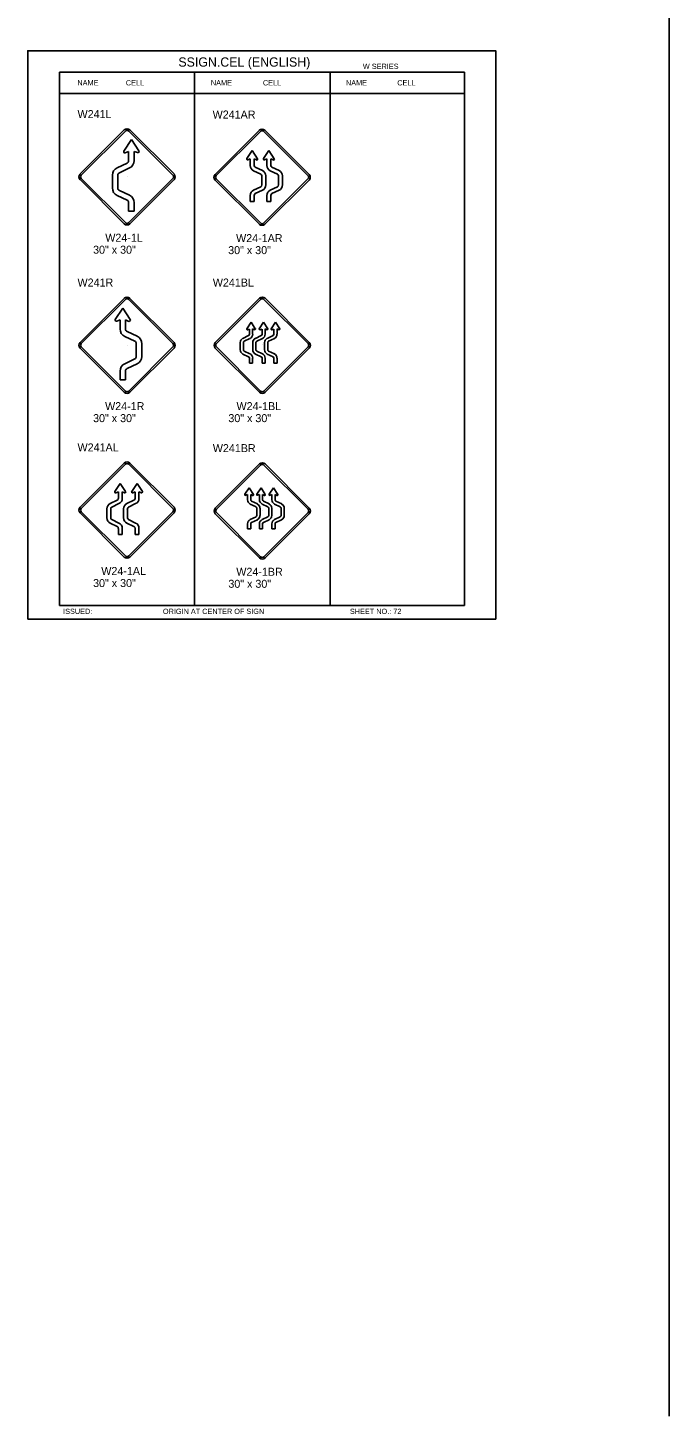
# Model space of a CAD drawing. Extents: x -5299 to 22597, y -19549 to -1808.
# Drawn here: x 4241 to 5202, y -9426 to -7343 of the extents above; entities that cross this region are included whole.
import ezdxf

# ---------------------------------------------------------------- set-up
doc = ezdxf.new("R2010")
doc.units = 0
for name, color, linetype in [('Level 1', 7, 'Continuous'), ('Level 2', 7, 'Continuous'), ('Level 3', 7, 'Continuous'), ('Level 62', 7, 'Continuous')]:
    doc.layers.add(name, color=color, linetype=linetype)

msp = doc.modelspace()

# ---------------------------------------------------------------- linework, layer by layer
at = {"layer": 'Level 1'}
for p, q in [((4895.6, -7410), (4288.6, -7410)), ((4288.6, -7410), (4288.6, -8210)), ((4490.9, -7410), (4490.9, -8210)), ((4694, -7410), (4694, -8210)), ((4895.6, -7410), (4895.6, -8210)), ((4895.6, -7441.7), (4288.6, -7441.7)), ((4385, -7528.4), (4396.3, -7511.1)), ((4396.3, -7511.1), (4407.4, -7528)), ((4392.2, -7528.9), (4387.2, -7530.9)), ((4392.2, -7542.5), (4392.2, -7528.9)), ((4400.4, -7542.5), (4400.4, -7528.8)), ((4405.4, -7530.6), (4400.4, -7528.8)), ((4569.3, -7539.4), (4577.2, -7527.4)), ((4577.2, -7527.4), (4585.3, -7539.7)), ((4594.4, -7539.4), (4602.3, -7527.4)), ((4602.3, -7527.4), (4610.3, -7539.7)), ((4374.8, -7553.4), (4389.8, -7546.2)), ((4378.4, -7560.8), (4393.4, -7553.6)), ((4574.3, -7540), (4570.8, -7541.3)), ((4574.3, -7549.8), (4574.3, -7540)), ((4590, -7562.8), (4579.3, -7557.7)), ((4583.7, -7541.5), (4580.2, -7540)), ((4580.2, -7540), (4580.2, -7549.8)), ((4581.8, -7552.4), (4592.5, -7557.5)), ((4599.4, -7540), (4595.8, -7541.3)), ((4599.4, -7549.8), (4599.4, -7540)), ((4615.1, -7562.8), (4604.4, -7557.7)), ((4608.8, -7541.5), (4605.3, -7540)), ((4605.3, -7540), (4605.3, -7549.8)), ((4606.9, -7552.4), (4617.6, -7557.5)), ((4367.8, -7583.6), (4367.8, -7564.5)), ((4376, -7583.6), (4376, -7564.5)), ((4389.9, -7565.9), (4389.9, -7565.9)), ((4591.6, -7565.8), (4591.6, -7565.8)), ((4591.7, -7579.1), (4591.7, -7565.5)), ((4597.5, -7565.5), (4597.5, -7579.1)), ((4616.8, -7579.1), (4616.8, -7565.5)), ((4622.6, -7565.5), (4622.6, -7579.1)), ((4374.8, -7594.7), (4389.8, -7601.9)), ((4378.4, -7587.3), (4393.4, -7594.5)), ((4574.3, -7603.9), (4574.3, -7594.7)), ((4579.3, -7586.8), (4590, -7581.7)), ((4580.2, -7594.7), (4580.2, -7603.9)), ((4592.5, -7587), (4581.8, -7592.1)), ((4599.4, -7603.9), (4599.4, -7594.7)), ((4604.4, -7586.8), (4615.1, -7581.7)), ((4605.3, -7594.7), (4605.3, -7603.9)), ((4617.6, -7587), (4606.9, -7592.1)), ((4392.2, -7618.5), (4392.2, -7605.6)), ((4392.2, -7618.5), (4400.4, -7618.5)), ((4400.4, -7618.5), (4400.4, -7605.6)), ((4580.2, -7603.9), (4574.3, -7603.9)), ((4605.3, -7603.9), (4599.4, -7603.9)), ((4383.4, -7763.8), (4372.2, -7780.6)), ((4394.6, -7781), (4383.4, -7763.8)), ((4374.3, -7783.2), (4379.3, -7781.4)), ((4379.3, -7795.1), (4379.3, -7781.4)), ((4387.5, -7795.1), (4387.5, -7781.5)), ((4387.5, -7781.5), (4392.5, -7783.6)), ((4575.7, -7785), (4569.2, -7794.8)), ((4582, -7794.6), (4575.7, -7785)), ((4594.4, -7785), (4587.9, -7794.8)), ((4600.7, -7794.6), (4594.4, -7785)), ((4612.1, -7785), (4605.7, -7794.8)), ((4618.5, -7794.6), (4612.1, -7785)), ((4401.3, -7813.4), (4386.3, -7806.3)), ((4404.8, -7806), (4389.8, -7798.8)), ((4572, -7805), (4563.4, -7809.1)), ((4570.5, -7796.3), (4573.3, -7795.1)), ((4573.3, -7795.1), (4573.3, -7802.9)), ((4578, -7802.9), (4578, -7795)), ((4578, -7795), (4580.8, -7796.1)), ((4590.7, -7805), (4582.1, -7809.1)), ((4589.2, -7796.3), (4592, -7795.1)), ((4592, -7795.1), (4592, -7802.9)), ((4596.7, -7802.9), (4596.7, -7795)), ((4596.7, -7795), (4599.5, -7796.1)), ((4608.5, -7805), (4599.9, -7809.1)), ((4606.9, -7796.3), (4609.8, -7795.1)), ((4609.8, -7795.1), (4609.8, -7802.9)), ((4614.5, -7802.9), (4614.5, -7795)), ((4614.5, -7795), (4617.3, -7796.1)), ((4389.9, -7819.5), (4389.9, -7819.5)), ((4403.6, -7836.2), (4403.6, -7817.1)), ((4411.8, -7836.2), (4411.8, -7817.1)), ((4559.4, -7815.4), (4559.4, -7826.3)), ((4564.1, -7826.3), (4564.1, -7815.4)), ((4565.4, -7813.3), (4574, -7809.2)), ((4574, -7832.5), (4565.4, -7828.4)), ((4578.1, -7815.4), (4578.1, -7826.3)), ((4582.8, -7826.3), (4582.8, -7815.4)), ((4584.1, -7813.3), (4592.7, -7809.2)), ((4592.7, -7832.5), (4584.1, -7828.4)), ((4592.5, -7818.9), (4592.5, -7818.9)), ((4595.9, -7815.4), (4595.9, -7826.3)), ((4600.6, -7826.3), (4600.6, -7815.4)), ((4601.9, -7813.3), (4610.5, -7809.2)), ((4610.5, -7832.5), (4601.9, -7828.4)), ((4401.3, -7839.9), (4386.3, -7847.1)), ((4404.8, -7847.3), (4389.8, -7854.5)), ((4563.4, -7832.6), (4572, -7836.7)), ((4573.3, -7838.8), (4573.3, -7846.2)), ((4573.3, -7846.2), (4578, -7846.2)), ((4578, -7846.2), (4578, -7838.8)), ((4582.1, -7832.6), (4590.7, -7836.7)), ((4592, -7838.8), (4592, -7846.2)), ((4592, -7846.2), (4596.7, -7846.2)), ((4596.7, -7846.2), (4596.7, -7838.8)), ((4599.9, -7832.6), (4608.5, -7836.7)), ((4609.8, -7838.8), (4609.8, -7846.2)), ((4609.8, -7846.2), (4614.5, -7846.2)), ((4614.5, -7846.2), (4614.5, -7838.8)), ((4379.3, -7871.1), (4379.3, -7858.2)), ((4387.5, -7871.1), (4379.3, -7871.1)), ((4387.5, -7871.1), (4387.5, -7858.2)), ((4379.7, -8026.7), (4371.7, -8039)), ((4387.7, -8038.7), (4379.7, -8026.7)), ((4404.8, -8026.7), (4396.8, -8039)), ((4412.7, -8038.7), (4404.8, -8026.7)), ((4566.4, -8043), (4572.7, -8033.4)), ((4572.7, -8033.4), (4579.2, -8043.2)), ((4584.1, -8043), (4590.5, -8033.4)), ((4590.5, -8033.4), (4596.9, -8043.2)), ((4602.8, -8043), (4609.2, -8033.4)), ((4609.2, -8033.4), (4615.6, -8043.2)), ((4375.1, -8051.7), (4364.4, -8056.8)), ((4366.9, -8062.1), (4377.6, -8057)), ((4373.2, -8040.8), (4376.8, -8039.3)), ((4376.8, -8039.3), (4376.8, -8049.1)), ((4382.6, -8049.1), (4382.6, -8039.3)), ((4382.6, -8039.3), (4386.2, -8040.6)), ((4400.2, -8051.7), (4389.5, -8056.8)), ((4392, -8062.1), (4402.7, -8057)), ((4398.3, -8040.8), (4401.8, -8039.3)), ((4401.8, -8039.3), (4401.8, -8049.1)), ((4407.7, -8049.1), (4407.7, -8039.3)), ((4407.7, -8039.3), (4411.3, -8040.6)), ((4570.4, -8043.5), (4567.5, -8044.5)), ((4570.4, -8051.3), (4570.4, -8043.5)), ((4583, -8061.8), (4574.4, -8057.7)), ((4577.9, -8044.7), (4575.1, -8043.5)), ((4575.1, -8043.5), (4575.1, -8051.3)), ((4576.4, -8053.4), (4585, -8057.5)), ((4588.2, -8043.5), (4585.3, -8044.5)), ((4588.2, -8051.3), (4588.2, -8043.5)), ((4600.7, -8061.8), (4592.2, -8057.7)), ((4595.7, -8044.7), (4592.9, -8043.5)), ((4592.9, -8043.5), (4592.9, -8051.3)), ((4594.2, -8053.4), (4602.8, -8057.5)), ((4606.9, -8043.5), (4604, -8044.5)), ((4606.9, -8051.3), (4606.9, -8043.5)), ((4619.4, -8061.8), (4610.9, -8057.7)), ((4614.4, -8044.7), (4611.6, -8043.5)), ((4611.6, -8043.5), (4611.6, -8051.3)), ((4612.9, -8053.4), (4621.5, -8057.5)), ((4359.4, -8064.8), (4359.4, -8078.4)), ((4365.3, -8078.4), (4365.3, -8064.8)), ((4384.5, -8064.8), (4384.5, -8078.4)), ((4388.9, -8065.7), (4388.9, -8065.7)), ((4390.3, -8078.4), (4390.3, -8064.8)), ((4574.4, -8081), (4583, -8076.9)), ((4584.3, -8074.8), (4584.3, -8063.9)), ((4589, -8063.9), (4589, -8074.8)), ((4592.2, -8067.4), (4592.2, -8067.4)), ((4592.2, -8081), (4600.7, -8076.9)), ((4602.1, -8074.8), (4602.1, -8063.9)), ((4606.7, -8063.9), (4606.7, -8074.8)), ((4610.9, -8081), (4619.4, -8076.9)), ((4620.8, -8074.8), (4620.8, -8063.9)), ((4625.4, -8063.9), (4625.4, -8074.8)), ((4364.4, -8086.3), (4375.1, -8091.4)), ((4377.6, -8086.1), (4366.9, -8081)), ((4376.8, -8094.1), (4376.8, -8103.3)), ((4382.6, -8103.3), (4382.6, -8094.1)), ((4389.5, -8086.3), (4400.2, -8091.4)), ((4402.7, -8086.1), (4392, -8081)), ((4401.8, -8094.1), (4401.8, -8103.3)), ((4407.7, -8103.3), (4407.7, -8094.1)), ((4570.4, -8094.7), (4570.4, -8087.3)), ((4575.1, -8094.7), (4570.4, -8094.7)), ((4575.1, -8087.3), (4575.1, -8094.7)), ((4585, -8081.1), (4576.4, -8085.2)), ((4588.2, -8094.7), (4588.2, -8087.3)), ((4592.9, -8094.7), (4588.2, -8094.7)), ((4592.9, -8087.3), (4592.9, -8094.7)), ((4602.8, -8081.1), (4594.2, -8085.2)), ((4606.9, -8094.7), (4606.9, -8087.3)), ((4611.6, -8094.7), (4606.9, -8094.7)), ((4611.6, -8087.3), (4611.6, -8094.7)), ((4621.4, -8081.1), (4612.9, -8085.2)), ((4376.8, -8103.3), (4382.6, -8103.3)), ((4401.8, -8103.3), (4407.7, -8103.3)), ((4288.6, -8210), (4895.6, -8210))]:
    msp.add_line(p, q, dxfattribs=at)
for centre, radius, start, end in [((4386.5, -7529.3), 1.76, 146.8887, 292.6199), ((4406, -7528.9), 1.76, 250.3462, 33.1113), ((4380.1, -7564.5), 12.3, 115.5835, 180), ((4388.1, -7542.5), 4.11, 295.5835, 0), ((4388.1, -7542.5), 12.3, 295.5835, 0), ((4570.3, -7540.1), 1.26, 146.8887, 289.6538), ((4583.1, -7549.8), 8.79, 180, 244.4165), ((4583.1, -7549.8), 2.93, 180, 244.4165), ((4584.2, -7540.4), 1.26, 247.3801, 33.1113), ((4588.8, -7565.5), 8.79, 0, 64.4165), ((4595.4, -7540.1), 1.26, 146.8887, 289.6538), ((4608.2, -7549.8), 8.79, 180, 244.4165), ((4608.2, -7549.8), 2.93, 180, 244.4165), ((4609.3, -7540.4), 1.26, 247.3801, 33.1113), ((4613.8, -7565.5), 8.79, 0, 64.4165), ((4380.1, -7564.5), 4.11, 115.5834, 180), ((4588.8, -7565.5), 2.93, 0, 64.4166), ((4588.8, -7579.1), 2.93, 295.5615, 0), ((4588.8, -7579.1), 8.79, 295.5615, 360), ((4613.8, -7565.5), 2.93, 0, 64.4166), ((4613.8, -7579.1), 2.93, 295.5615, 0), ((4613.8, -7579.1), 8.79, 295.5615, 360), ((4380.1, -7583.6), 12.3, 180, 244.4385), ((4380.1, -7583.6), 4.11, 180, 244.4385), ((4388.1, -7605.6), 12.3, 0, 64.4385), ((4583.1, -7594.7), 8.79, 115.5615, 180), ((4583.1, -7594.7), 2.93, 115.5616, 180), ((4608.2, -7594.7), 8.79, 115.5615, 180), ((4608.2, -7594.7), 2.93, 115.5616, 180), ((4388.1, -7605.6), 4.11, 0, 64.4384), ((4373.7, -7781.6), 1.76, 146.8887, 289.6538), ((4393.1, -7781.9), 1.76, 247.3801, 33.1113), ((4391.6, -7795.1), 12.3, 180, 244.4165), ((4391.6, -7795.1), 4.11, 180, 244.4165), ((4399.5, -7817.1), 12.3, 0, 64.4165), ((4566.4, -7815.4), 7.03, 115.5835, 180), ((4570.1, -7795.3), 1, 146.8887, 292.6199), ((4571, -7802.9), 2.34, 295.5835, 360), ((4571, -7802.9), 7.03, 295.5835, 0), ((4585.1, -7815.4), 7.03, 115.5835, 180), ((4581.2, -7795.1), 1, 250.3462, 33.1113), ((4588.8, -7795.3), 1, 146.8887, 292.6199), ((4589.7, -7802.9), 2.34, 295.5835, 360), ((4589.7, -7802.9), 7.03, 295.5835, 0), ((4602.9, -7815.4), 7.03, 115.5835, 180), ((4599.9, -7795.1), 1, 250.3462, 33.1113), ((4606.6, -7795.3), 1, 146.8887, 292.6199), ((4607.4, -7802.9), 2.34, 295.5835, 360), ((4607.4, -7802.9), 7.03, 295.5835, 0), ((4617.7, -7795.1), 1, 250.3462, 33.1113), ((4399.5, -7817.1), 4.11, 0, 64.4166), ((4566.4, -7826.3), 7.03, 180, 244.4385), ((4566.4, -7815.4), 2.34, 115.5834, 180), ((4566.4, -7826.3), 2.34, 180, 244.4385), ((4585.1, -7826.3), 7.03, 180, 244.4385), ((4585.1, -7815.4), 2.34, 115.5834, 180), ((4585.1, -7826.3), 2.34, 180, 244.4385), ((4602.9, -7826.3), 7.03, 180, 244.4385), ((4602.9, -7815.4), 2.34, 115.5834, 180), ((4602.9, -7826.3), 2.34, 180, 244.4385), ((4391.6, -7858.2), 12.3, 115.5615, 180), ((4399.5, -7836.2), 4.11, 295.5615, 0), ((4399.5, -7836.2), 12.3, 295.5615, 0), ((4571, -7838.8), 2.34, 0, 64.4384), ((4571, -7838.8), 7.03, 0, 64.4385), ((4589.7, -7838.8), 2.34, 0, 64.4384), ((4589.7, -7838.8), 7.03, 0, 64.4385), ((4607.4, -7838.8), 2.34, 0, 64.4384), ((4607.4, -7838.8), 7.03, 0, 64.4385), ((4391.6, -7858.2), 4.11, 115.5616, 180), ((4368.2, -8064.8), 8.79, 115.5835, 180), ((4372.7, -8039.7), 1.26, 146.8887, 292.6199), ((4373.8, -8049.1), 2.93, 295.5835, 360), ((4373.8, -8049.1), 8.79, 295.5835, 0), ((4393.3, -8064.8), 8.79, 115.5835, 180), ((4386.6, -8039.4), 1.26, 250.3462, 33.1113), ((4397.8, -8039.7), 1.26, 146.8887, 292.6199), ((4398.9, -8049.1), 2.93, 295.5835, 360), ((4398.9, -8049.1), 8.79, 295.5835, 0), ((4411.7, -8039.4), 1.26, 250.3462, 33.1113), ((4567.2, -8043.6), 1, 146.8887, 289.6538), ((4577.4, -8051.3), 7.03, 180, 244.4165), ((4577.4, -8051.3), 2.34, 180, 244.4165), ((4578.3, -8043.8), 1, 247.3801, 33.1113), ((4585, -8043.6), 1, 146.8887, 289.6538), ((4581.9, -8063.9), 7.03, 0, 64.4165), ((4595.2, -8051.3), 7.03, 180, 244.4165), ((4595.2, -8051.3), 2.34, 180, 244.4165), ((4596.1, -8043.8), 1, 247.3801, 33.1113), ((4603.7, -8043.6), 1, 146.8887, 289.6538), ((4599.7, -8063.9), 7.03, 0, 64.4165), ((4613.9, -8051.3), 7.03, 180, 244.4165), ((4613.9, -8051.3), 2.34, 180, 244.4165), ((4614.8, -8043.8), 1, 247.3801, 33.1113), ((4618.4, -8063.9), 7.03, 0, 64.4165), ((4368.2, -8078.4), 8.79, 180, 244.4385), ((4368.2, -8064.8), 2.93, 115.5834, 180), ((4368.2, -8078.4), 2.93, 180, 244.4385), ((4393.3, -8078.4), 8.79, 180, 244.4385), ((4393.3, -8064.8), 2.93, 115.5834, 180), ((4393.3, -8078.4), 2.93, 180, 244.4385), ((4581.9, -8063.9), 2.34, 0, 64.4166), ((4581.9, -8074.8), 2.34, 295.5615, 0), ((4581.9, -8074.8), 7.03, 295.5615, 360), ((4599.7, -8063.9), 2.34, 0, 64.4166), ((4599.7, -8074.8), 2.34, 295.5615, 0), ((4599.7, -8074.8), 7.03, 295.5615, 360), ((4618.4, -8063.9), 2.34, 0, 64.4166), ((4618.4, -8074.8), 2.34, 295.5615, 0), ((4618.4, -8074.8), 7.03, 295.5615, 360), ((4373.8, -8094.1), 2.93, 0, 64.4384), ((4373.8, -8094.1), 8.79, 0, 64.4385), ((4398.9, -8094.1), 2.93, 0, 64.4384), ((4398.9, -8094.1), 8.79, 0, 64.4385), ((4577.4, -8087.3), 7.03, 115.5615, 180), ((4577.4, -8087.3), 2.34, 115.5616, 180), ((4595.2, -8087.3), 7.03, 115.5615, 180), ((4595.2, -8087.3), 2.34, 115.5616, 180), ((4613.9, -8087.3), 7.03, 115.5615, 180), ((4613.9, -8087.3), 2.34, 115.5616, 180)]:
    msp.add_arc(centre, radius, start, end, dxfattribs=at)
at = {"layer": 'Level 3'}
for p, q in [((5202.1, -1877.7), (5202.1, -9425.7)), ((4319.4, -7562.6), (4385.6, -7496.4)), ((4394, -7496.4), (4460.3, -7562.6)), ((4321.1, -7564.4), (4387.3, -7498.2)), ((4392.3, -7498.2), (4458.5, -7564.4)), ((4588, -7497), (4521.8, -7563.2)), ((4589.7, -7498.7), (4523.5, -7564.9)), ((4660.9, -7564.9), (4594.7, -7498.7)), ((4662.6, -7563.2), (4596.4, -7497)), ((4385.6, -7637.3), (4319.4, -7571.1)), ((4387.3, -7635.6), (4321.1, -7569.4)), ((4458.5, -7569.4), (4392.3, -7635.6)), ((4460.3, -7571.1), (4394, -7637.3)), ((4521.8, -7571.7), (4588, -7637.9)), ((4523.5, -7569.9), (4589.7, -7636.1)), ((4594.7, -7636.1), (4660.9, -7569.9)), ((4596.4, -7637.9), (4662.6, -7571.7)), ((4385.6, -7749.1), (4319.4, -7815.3)), ((4387.3, -7750.8), (4321.1, -7817)), ((4458.5, -7817), (4392.3, -7750.8)), ((4460.3, -7815.3), (4394, -7749.1)), ((4522, -7815.2), (4588.2, -7749)), ((4523.7, -7816.9), (4589.9, -7750.7)), ((4594.9, -7750.7), (4661.1, -7816.9)), ((4596.7, -7749), (4662.9, -7815.2)), ((4319.4, -7823.7), (4385.6, -7889.9)), ((4321.1, -7822), (4387.3, -7888.2)), ((4392.3, -7888.2), (4458.5, -7822)), ((4394, -7889.9), (4460.3, -7823.7)), ((4588.2, -7889.9), (4522, -7823.7)), ((4589.9, -7888.1), (4523.7, -7821.9)), ((4661.1, -7821.9), (4594.9, -7888.1)), ((4662.9, -7823.7), (4596.7, -7889.9)), ((4319.4, -8062.5), (4385.6, -7996.3)), ((4394, -7996.3), (4460.3, -8062.5)), ((4321.1, -8064.3), (4387.3, -7998)), ((4392.3, -7998), (4458.5, -8064.3)), ((4588.2, -7997.5), (4522, -8063.7)), ((4589.9, -7999.2), (4523.7, -8065.4)), ((4661.1, -8065.4), (4594.9, -7999.2)), ((4662.9, -8063.7), (4596.7, -7997.5)), ((4385.6, -8137.2), (4319.4, -8071)), ((4387.3, -8135.4), (4321.1, -8069.2)), ((4458.5, -8069.2), (4392.3, -8135.4)), ((4460.3, -8071), (4394, -8137.2)), ((4522, -8072.1), (4588.2, -8138.3)), ((4523.7, -8070.4), (4589.9, -8136.6)), ((4594.9, -8136.6), (4661.1, -8070.4)), ((4596.7, -8138.3), (4662.9, -8072.1))]:
    msp.add_line(p, q, dxfattribs=at)
for centre, radius, start, end in [((4389.8, -7500.7), 5.98, 45, 135), ((4592.2, -7501.2), 5.98, 45, 135), ((4389.8, -7500.7), 3.52, 45, 135), ((4592.2, -7501.2), 3.52, 45, 135), ((4323.6, -7566.9), 5.98, 135, 225), ((4323.6, -7566.9), 3.52, 135, 225), ((4456, -7566.9), 3.52, 315, 45), ((4456, -7566.9), 5.98, 315, 45), ((4526, -7567.4), 5.98, 135, 225), ((4526, -7567.4), 3.52, 135, 225), ((4658.4, -7567.4), 3.52, 315, 45), ((4658.4, -7567.4), 5.98, 315, 45), ((4389.8, -7633.1), 5.98, 225, 315), ((4389.8, -7633.1), 3.52, 225, 315), ((4592.2, -7633.6), 5.98, 225, 315), ((4592.2, -7633.6), 3.52, 225, 315), ((4389.8, -7753.3), 5.98, 45, 135), ((4389.8, -7753.3), 3.52, 45, 135), ((4592.4, -7753.2), 5.98, 45, 135), ((4592.4, -7753.2), 3.52, 45, 135), ((4323.6, -7819.5), 5.98, 135, 225), ((4323.6, -7819.5), 3.52, 135, 225), ((4456, -7819.5), 3.52, 315, 45), ((4456, -7819.5), 5.98, 315, 45), ((4526.2, -7819.4), 5.98, 135, 225), ((4526.2, -7819.4), 3.52, 135, 225), ((4658.6, -7819.4), 3.52, 315, 45), ((4658.6, -7819.4), 5.98, 315, 45), ((4389.8, -7885.7), 5.98, 225, 315), ((4389.8, -7885.7), 3.52, 225, 315), ((4592.4, -7885.6), 5.98, 225, 315), ((4592.4, -7885.6), 3.52, 225, 315), ((4389.8, -8000.5), 5.98, 45, 135), ((4592.4, -8001.7), 5.98, 45, 135), ((4389.8, -8000.5), 3.52, 45, 135), ((4592.4, -8001.7), 3.52, 45, 135), ((4323.6, -8066.7), 5.98, 135, 225), ((4323.6, -8066.7), 3.52, 135, 225), ((4456, -8066.7), 3.52, 315, 45), ((4456, -8066.7), 5.98, 315, 45), ((4526.2, -8067.9), 5.98, 135, 225), ((4526.2, -8067.9), 3.52, 135, 225), ((4658.6, -8067.9), 3.52, 315, 45), ((4658.6, -8067.9), 5.98, 315, 45), ((4389.8, -8133), 5.98, 225, 315), ((4389.8, -8133), 3.52, 225, 315), ((4592.4, -8134.1), 5.98, 225, 315), ((4592.4, -8134.1), 3.52, 225, 315)]:
    msp.add_arc(centre, radius, start, end, dxfattribs=at)
at = {"layer": 'Level 62'}
msp.add_lwpolyline([(4241.1, -8230.2), (4942.1, -8230.2), (4942.1, -7377.8), (4241.1, -7377.8)], close=True, dxfattribs=at)

# ---------------------------------------------------------------- texts
at = {"layer": 'Level 2'}
for s, p in [('W241L', (4315.6, -7478.8)), ('W241AR', (4518, -7479.4)), ('W241R', (4315.6, -7731.4)), ('W241BL', (4518.3, -7731.4)), ('W241AL', (4315.6, -7978.7)), ('W241BR', (4518.3, -7979.8))]:
    msp.add_text(s, height=12, dxfattribs=at).set_placement(p)
at = {"layer": 'Level 3'}
for s, height, p in [('SSIGN.CEL (ENGLISH)', 13.857, (4466.7, -7401.6)), ('W SERIES', 7.92, (4743.1, -7405.1)), ('NAME', 7.92, (4315.4, -7429.8)), ('CELL', 7.92, (4388, -7429.8)), ('NAME', 7.92, (4515.4, -7429.8)), ('CELL', 7.92, (4593.4, -7429.8)), ('NAME', 7.92, (4717.8, -7429.8)), ('CELL', 7.92, (4794.7, -7429.8)), ('W24-1L', 12, (4357.2, -7664.2)), ('W24-1AR', 12, (4553.2, -7664.8)), ('30" x 30"', 12, (4338.9, -7682.2)), ('30" x 30"', 12, (4541.3, -7682.8)), ('W24-1R', 12, (4356.9, -7916.8)), ('W24-1BL', 12, (4553.8, -7916.8)), ('30" x 30"', 12, (4338.9, -7934.8)), ('30" x 30"', 12, (4541.6, -7934.8)), ('W24-1AL', 12, (4351.2, -8164.1)), ('W24-1BR', 12, (4553.5, -8165.2)), ('30" x 30"', 12, (4338.9, -8182.1)), ('30" x 30"', 12, (4541.6, -8183.2)), ('ISSUED:', 7.92, (4294, -8222.5)), ('ORIGIN AT CENTER OF SIGN', 7.918, (4443.5, -8222.5)), ('SHEET NO.: 72', 7.918, (4723.7, -8222.5))]:
    msp.add_text(s, height=height, dxfattribs=at).set_placement(p)

doc.saveas('drawing.dxf')
